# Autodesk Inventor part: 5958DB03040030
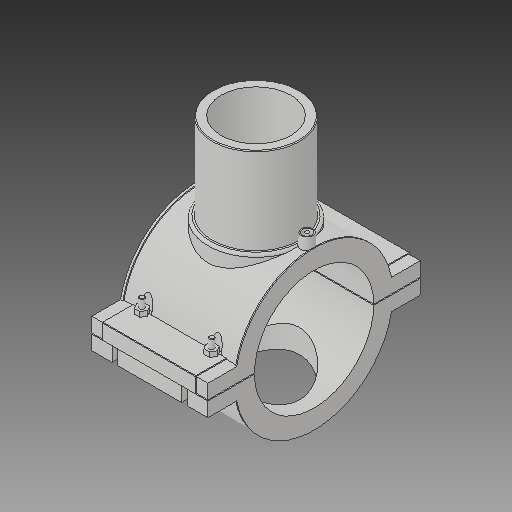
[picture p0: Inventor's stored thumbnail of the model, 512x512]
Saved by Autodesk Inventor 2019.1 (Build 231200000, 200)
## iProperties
Created: 2017-07
Part Number: 5958DB03040030
Material: Generic
Description: PLASSON BRANCH SADDLE 4''DIPS x 3''IPS
Document SubType Name: Modeling
Designer: KIM
Mass: 764.267 g
Surface Area: 1930.38 cm^2
Volume: 764.267 cm^3
Density: 1 g/cm^3
Appearance: Default
Author: KIM
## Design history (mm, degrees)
derived "5958D (1).ipt"
feature "Solid6::5958D (1).ipt"
feature "Solid7::5958D (1).ipt"
feature "Solid8::5958D (1).ipt"
tag "TaggingFeature1"
body "Solid1"
body "Solid2"
body "Solid3"
other parameters: "d244" = 121.3, "d245" = 18.288, "d246" = 30.325, "d247" = 30.325, "d248" = 215.9, "d249" = 107.95, "d250" = 1, "d252" = 60.65, "d253" = 60.65, "d254" = 18.288, "d255" = 18.288, "d256" = 215.9, "d257" = 15.1625, "d258" = 107.95, "d259" = 0.5, "d260" = 118.11, "d261" = 0, "d262" = 70.866, "d263" = 6, "d271" = 0, "d272" = 3, "d274" = 3, "d277" = 3, "d278" = 3, "d279" = 5.4, "d280" = 0, "d281" = 0, "d283" = 30.325, "d284" = 0.6, "d287" = 79.66952, "d288" = 97.57, "d290" = 0, "d291" = 167.584, "d292" = 88.7, "d294" = 0, "d295" = 3, "d296" = 15, "d297" = 15, "d298" = 25.4, "d299" = 0, "d300" = 1, "d302" = 94.488, "d303" = 0, "d306" = 5, "d307" = 0, "d308" = 1, "d309" = 90.65, "d310" = 12, "d311" = 12, "d315" = 3 deg, "d316" = 4, "d318" = 4, "d320" = 14, "d321" = 0, "d322" = 0.5, "d323" = 1.213, "d324" = 1.213, "d325" = 2.3622, "d326" = 0, "d327" = 1.1811, "d328" = 1.1811, "d329" = 1.1811, "d330" = 0, "d331" = 2.661, "d332" = 70.96, "d334" = 0, "d336" = 0, "d337" = 0.887, "d340" = 7.0866, "d341" = 7.0866, "d_" = 121.3, "d1" = 88.7, "B_" = 215.9, "H_" = 106.934, "H1" = 88.646, "L" = 118.11, "t" = 6
